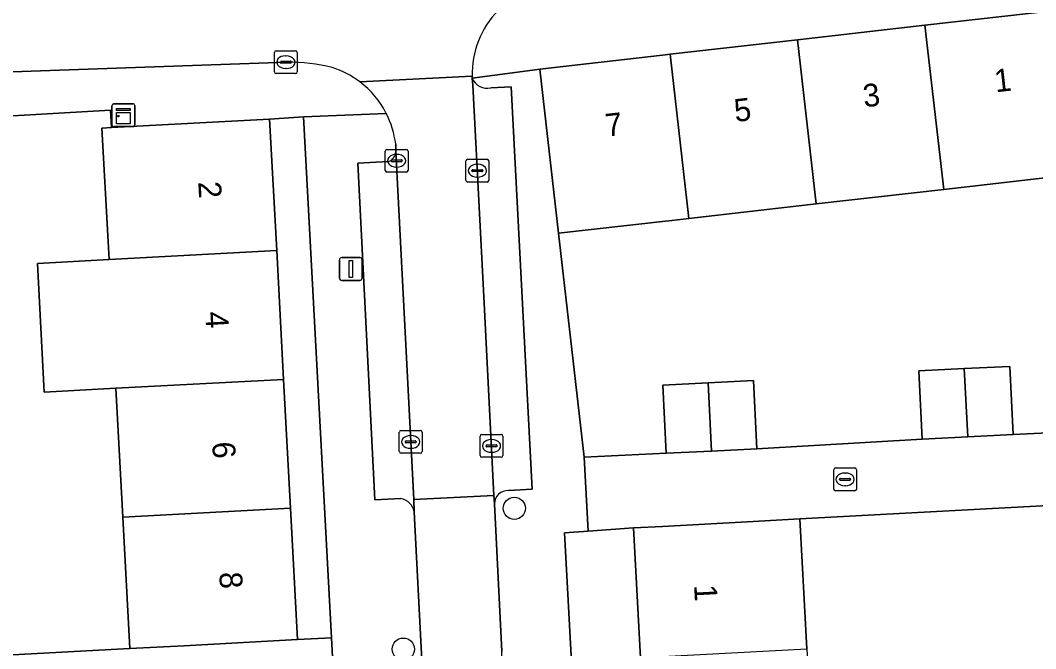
# Model space of a CAD drawing. Extents: x 162250 to 162661, y 380743 to 381606.
# Drawn here: x 162471.8 to 162516.38, y 380866.07 to 380893.67 of the extents above; entities that cross this region are included whole.
import ezdxf

# ---------------------------------------------------------------- set-up
doc = ezdxf.new("R2010")
doc.units = 0
for name, color, linetype in [('IMGEO_Boom', 7, 'Continuous'), ('IMGEO_Erf', 7, 'Continuous'), ('IMGEO_Kast', 7, 'Continuous'), ('IMGEO_Kolk', 7, 'Continuous'), ('IMGEO_Lichtmast', 7, 'Continuous'), ('IMGEO_Muur', 7, 'Continuous'), ('IMGEO_Pand', 7, 'Continuous'), ('IMGEO_Pand_nummerreeks', 7, 'Continuous'), ('IMGEO_Parkeervlak_open', 7, 'Continuous'), ('IMGEO_Rijbaan_lokaal_open', 7, 'Continuous'), ('IMGEO_Voetpad_open', 7, 'Continuous')]:
    doc.layers.add(name, color=color, linetype=linetype)

msp = doc.modelspace()

# ---------------------------------------------------------------- linework, layer by layer
at = {"layer": 'IMGEO_Boom'}
for centre in [(162493.492, 380872.237), (162488.619, 380866.049)]:
    msp.add_circle(centre, 0.489, dxfattribs=at)
at = {"layer": 'IMGEO_Erf'}
for points in [[(162476.003, 380877.506), (162472.856, 380877.338), (162472.553, 380882.993), (162475.699, 380883.161), (162475.657, 380883.948), (162475.388, 380888.933), (162475.802, 380888.955), (162475.764, 380889.728), (162473.498, 380889.596), (162463.611, 380889.016), (162463.383, 380889.008), (162463.524, 380884.867), (162467.402, 380885), (162467.48, 380882.72), (162467.564, 380880.294), (162463.905, 380880.169), (162464.132, 380873.557), (162468.01, 380873.69), (162468.088, 380871.41), (162468.172, 380868.984), (162464.294, 380868.851), (162464.412, 380865.42), (162476.618, 380866.074), (162476.307, 380871.851)], [(162484.236, 380889.431), (162482.75, 380889.328), (162483.06, 380883.556), (162483.364, 380877.9), (162483.668, 380872.246), (162483.979, 380866.47), (162485.462, 380866.549)], [(162518.058, 380886.891), (162512.345, 380886.245), (162506.75, 380885.606), (162501.155, 380884.966), (162500.406, 380884.88), (162500, 380884.834), (162495.438, 380884.313), (162496.559, 380874.478), (162500.151, 380874.654), (162500.005, 380877.65), (162501.998, 380877.747), (162503.992, 380877.845), (162504.138, 380874.849), (162511.4, 380875.277), (162511.253, 380878.273), (162513.247, 380878.371), (162515.24, 380878.468), (162515.387, 380875.472), (162519.087, 380875.653)], [(162500.535, 380837.761), (162500.235, 380843.344), (162500, 380847.679), (162499.934, 380848.927), (162499.634, 380854.509), (162499.333, 380860.091), (162499.032, 380865.673), (162498.723, 380871.373), (162496.735, 380871.229), (162495.691, 380871.164), (162499.625, 380798.455), (162500, 380798.466), (162501.095, 380798.5), (162502.647, 380798.565), (162502.34, 380804.267), (162502.039, 380809.849), (162501.738, 380815.432), (162501.437, 380821.014), (162501.136, 380826.596), (162500.835, 380832.179)]]:
    msp.add_lwpolyline(points, close=True, dxfattribs=at)
msp.add_lwpolyline([(162519.127, 380872.478), (162506.03, 380871.77), (162506.34, 380866.068), (162506.643, 380860.485), (162506.946, 380854.903), (162507.25, 380849.322), (162507.553, 380843.739), (162507.856, 380838.156), (162508.16, 380832.575), (162508.463, 380826.992), (162508.766, 380821.409)], dxfattribs=at)
at = {"layer": 'IMGEO_Kast'}
for p, q in [((162475.827, 380889.074), (162475.827, 380889.915)), ((162475.827, 380889.915), (162475.827, 380889.074)), ((162475.902, 380889.999), (162476.743, 380889.999)), ((162476.743, 380889.999), (162475.902, 380889.999)), ((162476.827, 380889.924), (162476.827, 380889.083)), ((162476.827, 380889.083), (162476.827, 380889.924)), ((162476.752, 380888.999), (162475.911, 380888.999)), ((162475.911, 380888.999), (162476.752, 380888.999))]:
    msp.add_line(p, q, dxfattribs=at)
for points in [[(162476.022, 380889.789), (162476.622, 380889.789), (162476.622, 380889.704), (162476.022, 380889.704), (162476.022, 380889.789)], [(162476.022, 380889.614), (162476.622, 380889.614), (162476.622, 380889.125), (162476.022, 380889.125), (162476.022, 380889.614)]]:
    msp.add_lwpolyline(points, dxfattribs=at)
msp.add_circle((162476.106, 380889.463), 0.0377, dxfattribs=at)
for centre, start, end in [((162475.905, 380889.921), 92.4484, 184.2845), ((162475.905, 380889.921), 92.4484, 184.2845), ((162476.749, 380889.921), 2.4484, 94.2845), ((162476.749, 380889.921), 2.4484, 94.2845), ((162475.905, 380889.077), 182.4484, 274.2845), ((162475.905, 380889.077), 182.4484, 274.2845), ((162476.749, 380889.077), 272.4484, 4.2845), ((162476.749, 380889.077), 272.4484, 4.2845)]:
    msp.add_arc(centre, 0.0779, start, end, dxfattribs=at)
at = {"layer": 'IMGEO_Kolk'}
for p, q in [((162482.962, 380891.404), (162482.962, 380892.256)), ((162483.037, 380892.33), (162483.889, 380892.33)), ((162483.45, 380892.11), (162483.475, 380892.11)), ((162483.963, 380892.256), (162483.963, 380891.404)), ((162483.221, 380891.824), (162483.221, 380891.836)), ((162483.659, 380891.787), (162483.261, 380891.787)), ((162483.264, 380891.873), (162483.662, 380891.873)), ((162483.705, 380891.836), (162483.705, 380891.824)), ((162483.889, 380891.33), (162483.037, 380891.33)), ((162483.473, 380891.55), (162483.448, 380891.55)), ((162487.827, 380887.075), (162487.827, 380887.927)), ((162487.902, 380888.001), (162488.754, 380888.001)), ((162488.315, 380887.781), (162488.34, 380887.781)), ((162488.828, 380887.927), (162488.828, 380887.075)), ((162488.086, 380887.495), (162488.086, 380887.507)), ((162488.524, 380887.458), (162488.126, 380887.458)), ((162488.129, 380887.544), (162488.527, 380887.544)), ((162488.338, 380887.221), (162488.313, 380887.221)), ((162488.57, 380887.507), (162488.57, 380887.495)), ((162491.37, 380886.638), (162491.37, 380887.49)), ((162491.445, 380887.564), (162492.297, 380887.564)), ((162491.858, 380887.344), (162491.883, 380887.344)), ((162492.371, 380887.49), (162492.371, 380886.638)), ((162488.754, 380887.001), (162487.902, 380887.001)), ((162491.629, 380887.058), (162491.629, 380887.07)), ((162492.067, 380887.021), (162491.669, 380887.021)), ((162491.672, 380887.107), (162492.07, 380887.107)), ((162491.881, 380886.784), (162491.856, 380886.784)), ((162492.113, 380887.07), (162492.113, 380887.058)), ((162492.297, 380886.564), (162491.445, 380886.564)), ((162488.443, 380874.728), (162488.443, 380875.58)), ((162488.518, 380875.654), (162489.37, 380875.654)), ((162489.444, 380875.58), (162489.444, 380874.728)), ((162488.702, 380875.148), (162488.702, 380875.16)), ((162489.14, 380875.111), (162488.742, 380875.111)), ((162488.745, 380875.197), (162489.143, 380875.197)), ((162488.931, 380875.434), (162488.956, 380875.434)), ((162489.186, 380875.16), (162489.186, 380875.148)), ((162491.99, 380874.552), (162491.99, 380875.404)), ((162492.065, 380875.478), (162492.917, 380875.478)), ((162492.478, 380875.258), (162492.503, 380875.258)), ((162492.991, 380875.404), (162492.991, 380874.552)), ((162489.37, 380874.654), (162488.518, 380874.654)), ((162488.954, 380874.874), (162488.929, 380874.874)), ((162492.249, 380874.972), (162492.249, 380874.984)), ((162492.687, 380874.935), (162492.289, 380874.935)), ((162492.292, 380875.021), (162492.69, 380875.021)), ((162492.501, 380874.698), (162492.476, 380874.698)), ((162492.733, 380874.984), (162492.733, 380874.972)), ((162492.917, 380874.478), (162492.065, 380874.478)), ((162507.513, 380873.081), (162507.513, 380873.933)), ((162507.588, 380874.007), (162508.44, 380874.007)), ((162508.001, 380873.787), (162508.026, 380873.787)), ((162508.514, 380873.933), (162508.514, 380873.081)), ((162507.772, 380873.501), (162507.772, 380873.513)), ((162508.21, 380873.464), (162507.812, 380873.464)), ((162507.815, 380873.55), (162508.213, 380873.55)), ((162508.256, 380873.513), (162508.256, 380873.501)), ((162508.44, 380873.007), (162507.588, 380873.007)), ((162508.024, 380873.227), (162507.999, 380873.227))]:
    msp.add_line(p, q, dxfattribs=at)
for points in [[(162482.962, 380891.404), (162482.962, 380892.256)], [(162483.037, 380892.33), (162483.889, 380892.33)], [(162483.963, 380892.256), (162483.963, 380891.404)], [(162483.889, 380891.33), (162483.037, 380891.33)], [(162487.827, 380887.075), (162487.827, 380887.927)], [(162487.902, 380888.001), (162488.754, 380888.001)], [(162488.828, 380887.927), (162488.828, 380887.075)], [(162491.37, 380886.638), (162491.37, 380887.49)], [(162491.445, 380887.564), (162492.297, 380887.564)], [(162492.371, 380887.49), (162492.371, 380886.638)], [(162488.754, 380887.001), (162487.902, 380887.001)], [(162492.297, 380886.564), (162491.445, 380886.564)], [(162488.443, 380874.728), (162488.443, 380875.58)], [(162488.518, 380875.654), (162489.37, 380875.654)], [(162489.444, 380875.58), (162489.444, 380874.728)], [(162491.99, 380874.552), (162491.99, 380875.404)], [(162492.065, 380875.478), (162492.917, 380875.478)], [(162492.991, 380875.404), (162492.991, 380874.552)], [(162489.37, 380874.654), (162488.518, 380874.654)], [(162492.917, 380874.478), (162492.065, 380874.478)], [(162507.513, 380873.081), (162507.513, 380873.933)], [(162507.588, 380874.007), (162508.44, 380874.007)], [(162508.514, 380873.933), (162508.514, 380873.081)], [(162508.44, 380873.007), (162507.588, 380873.007)]]:
    msp.add_lwpolyline(points, dxfattribs=at)
for centre, radius, start, end in [((162483.039, 380892.254), 0.0765, 91.552, 178.448), ((162483.039, 380892.254), 0.0765, 91.552, 178.448), ((162483.887, 380892.254), 0.0765, 1.552, 88.448), ((162483.887, 380892.254), 0.0765, 1.552, 88.448), ((162483.261, 380891.833), 0.0403, 85.8775, 175.7526), ((162483.258, 380891.823), 0.0366, 178.938, 274.7102), ((162483.662, 380891.83), 0.043, 264.8664, 352.4533), ((162483.666, 380891.835), 0.0386, 1.7309, 96.639), ((162483.039, 380891.406), 0.0765, 181.552, 268.448), ((162483.039, 380891.406), 0.0765, 181.552, 268.448), ((162483.887, 380891.406), 0.0765, 271.552, 358.448), ((162483.887, 380891.406), 0.0765, 271.552, 358.448), ((162487.904, 380887.925), 0.0765, 91.552, 178.448), ((162487.904, 380887.925), 0.0765, 91.552, 178.448), ((162488.752, 380887.925), 0.0765, 1.552, 88.448), ((162488.752, 380887.925), 0.0765, 1.552, 88.448), ((162488.126, 380887.504), 0.0403, 85.8775, 175.7526), ((162488.123, 380887.494), 0.0366, 178.938, 274.7102), ((162488.527, 380887.501), 0.043, 264.8664, 352.4533), ((162488.531, 380887.506), 0.0386, 1.7309, 96.639), ((162491.447, 380887.488), 0.0765, 91.552, 178.448), ((162491.447, 380887.488), 0.0765, 91.552, 178.448), ((162492.295, 380887.488), 0.0765, 1.552, 88.448), ((162492.295, 380887.488), 0.0765, 1.552, 88.448), ((162487.904, 380887.077), 0.0765, 181.552, 268.448), ((162487.904, 380887.077), 0.0765, 181.552, 268.448), ((162488.752, 380887.077), 0.0765, 271.552, 358.448), ((162488.752, 380887.077), 0.0765, 271.552, 358.448), ((162491.669, 380887.067), 0.0403, 85.8775, 175.7526), ((162491.666, 380887.057), 0.0366, 178.938, 274.7102), ((162492.07, 380887.064), 0.043, 264.8664, 352.4533), ((162492.074, 380887.069), 0.0386, 1.7309, 96.639), ((162491.447, 380886.64), 0.0765, 181.552, 268.448), ((162491.447, 380886.64), 0.0765, 181.552, 268.448), ((162492.295, 380886.64), 0.0765, 271.552, 358.448), ((162492.295, 380886.64), 0.0765, 271.552, 358.448), ((162488.52, 380875.578), 0.0765, 91.552, 178.448), ((162488.52, 380875.578), 0.0765, 91.552, 178.448), ((162489.368, 380875.578), 0.0765, 1.552, 88.448), ((162489.368, 380875.578), 0.0765, 1.552, 88.448), ((162488.742, 380875.157), 0.0403, 85.8775, 175.7526), ((162488.739, 380875.147), 0.0366, 178.938, 274.7102), ((162489.143, 380875.154), 0.043, 264.8664, 352.4533), ((162489.147, 380875.159), 0.0386, 1.7309, 96.639), ((162492.067, 380875.402), 0.0765, 91.552, 178.448), ((162492.067, 380875.402), 0.0765, 91.552, 178.448), ((162492.915, 380875.402), 0.0765, 1.552, 88.448), ((162492.915, 380875.402), 0.0765, 1.552, 88.448), ((162488.52, 380874.73), 0.0765, 181.552, 268.448), ((162488.52, 380874.73), 0.0765, 181.552, 268.448), ((162489.368, 380874.73), 0.0765, 271.552, 358.448), ((162489.368, 380874.73), 0.0765, 271.552, 358.448), ((162492.289, 380874.981), 0.0403, 85.8775, 175.7526), ((162492.286, 380874.971), 0.0366, 178.938, 274.7102), ((162492.69, 380874.978), 0.043, 264.8664, 352.4533), ((162492.694, 380874.983), 0.0386, 1.7309, 96.639), ((162492.067, 380874.554), 0.0765, 181.552, 268.448), ((162492.067, 380874.554), 0.0765, 181.552, 268.448), ((162492.915, 380874.554), 0.0765, 271.552, 358.448), ((162492.915, 380874.554), 0.0765, 271.552, 358.448), ((162507.59, 380873.931), 0.0765, 91.552, 178.448), ((162507.59, 380873.931), 0.0765, 91.552, 178.448), ((162508.438, 380873.931), 0.0765, 1.552, 88.448), ((162508.438, 380873.931), 0.0765, 1.552, 88.448), ((162507.812, 380873.51), 0.0403, 85.8775, 175.7526), ((162507.809, 380873.5), 0.0366, 178.938, 274.7102), ((162508.213, 380873.507), 0.043, 264.8664, 352.4533), ((162508.217, 380873.512), 0.0386, 1.7309, 96.639), ((162507.59, 380873.083), 0.0765, 181.552, 268.448), ((162507.59, 380873.083), 0.0765, 181.552, 268.448), ((162508.438, 380873.083), 0.0765, 271.552, 358.448), ((162508.438, 380873.083), 0.0765, 271.552, 358.448)]:
    msp.add_arc(centre, radius, start, end, dxfattribs=at)
for centre, major_axis, ratio, start_param, end_param in [((162483.449, 380891.83), (-0.387, 0.002), 0.722429, 4.712389, 7.853982), ((162483.474, 380891.83), (-0.39, 0.002), 0.717154, 1.570796, 4.712389), ((162488.314, 380887.501), (-0.387, 0.002), 0.722429, 4.712389, 7.853982), ((162488.339, 380887.501), (-0.39, 0.002), 0.717154, 1.570796, 4.712389), ((162491.857, 380887.064), (-0.387, 0.002), 0.722429, 4.712389, 7.853982), ((162491.882, 380887.064), (-0.39, 0.002), 0.717154, 1.570796, 4.712389), ((162488.93, 380875.154), (-0.387, 0.002), 0.722429, 4.712389, 7.853982), ((162488.955, 380875.154), (-0.39, 0.002), 0.717154, 1.570796, 4.712389), ((162492.477, 380874.978), (-0.387, 0.002), 0.722429, 4.712389, 7.853982), ((162492.502, 380874.978), (-0.39, 0.002), 0.717154, 1.570796, 4.712389), ((162508, 380873.507), (-0.387, 0.002), 0.722429, 4.712389, 7.853982), ((162508.025, 380873.507), (-0.39, 0.002), 0.717154, 1.570796, 4.712389)]:
    msp.add_ellipse(centre, major_axis=major_axis, ratio=ratio, start_param=start_param, end_param=end_param, dxfattribs=at)
at = {"layer": 'IMGEO_Lichtmast'}
for p, q in [((162485.815, 380882.348), (162485.815, 380883.148)), ((162485.815, 380883.148), (162485.815, 380882.348)), ((162485.915, 380883.248), (162486.705, 380883.248)), ((162486.705, 380883.248), (162485.915, 380883.248)), ((162486.805, 380883.148), (162486.805, 380882.348)), ((162486.805, 380882.348), (162486.805, 380883.148)), ((162486.705, 380882.248), (162485.915, 380882.248)), ((162485.915, 380882.248), (162486.705, 380882.248))]:
    msp.add_line(p, q, dxfattribs=at)
msp.add_lwpolyline([(162486.235, 380883.123), (162486.385, 380883.123), (162486.385, 380882.373), (162486.235, 380882.373), (162486.235, 380883.123)], dxfattribs=at)
for centre, start, end in [((162485.915, 380883.148), 90, 180), ((162485.915, 380883.148), 90, 180), ((162486.705, 380883.148), 0, 90), ((162486.705, 380883.148), 360, 90), ((162485.915, 380882.348), 180, 270), ((162485.915, 380882.348), 180, 270), ((162486.705, 380882.348), 270, 0), ((162486.705, 380882.348), 270, 0)]:
    msp.add_arc(centre, 0.1, start, end, dxfattribs=at)
at = {"layer": 'IMGEO_Muur'}
msp.add_lwpolyline([(162475.802, 380888.955), (162475.764, 380889.728), (162473.498, 380889.596)], dxfattribs=at)
at = {"layer": 'IMGEO_Pand'}
for points in [[(162511.52, 380893.448), (162512.345, 380886.245), (162518.058, 380886.891), (162517.802, 380889.133), (162517.236, 380894.1)], [(162511.52, 380893.448), (162505.925, 380892.811), (162506.75, 380885.606), (162512.345, 380886.245)], [(162506.75, 380885.606), (162505.925, 380892.811), (162500.33, 380892.174), (162501.155, 380884.966)], [(162501.155, 380884.966), (162500.33, 380892.174), (162500, 380892.136), (162494.616, 380891.523), (162495.438, 380884.313), (162500, 380884.834), (162500.406, 380884.88)], [(162475.699, 380883.161), (162483.06, 380883.556), (162482.75, 380889.328), (162475.802, 380888.955), (162475.388, 380888.933), (162475.657, 380883.948)], [(162476.003, 380877.506), (162483.364, 380877.9), (162483.06, 380883.556), (162475.699, 380883.161), (162472.553, 380882.993), (162472.856, 380877.338)], [(162513.247, 380878.371), (162511.253, 380878.273), (162511.4, 380875.277), (162513.394, 380875.375)], [(162513.247, 380878.371), (162513.394, 380875.375), (162515.387, 380875.472), (162515.24, 380878.468)], [(162476.003, 380877.506), (162476.307, 380871.851), (162483.668, 380872.246), (162483.364, 380877.9)], [(162501.998, 380877.747), (162502.145, 380874.751), (162504.138, 380874.849), (162503.992, 380877.845)], [(162501.998, 380877.747), (162500.005, 380877.65), (162500.151, 380874.654), (162502.145, 380874.751)], [(162483.668, 380872.246), (162476.307, 380871.851), (162476.618, 380866.074), (162478.987, 380866.201), (162483.979, 380866.47)], [(162499.032, 380865.673), (162500, 380865.725), (162506.34, 380866.068), (162506.03, 380871.77), (162503.716, 380871.645), (162500, 380871.443), (162498.723, 380871.373)]]:
    msp.add_lwpolyline(points, close=True, dxfattribs=at)
at = {"layer": 'IMGEO_Parkeervlak_open'}
for points in [[(162491.648, 380891.122), (162491.675, 380890.818), (162492.17, 380881.246), (162492.599, 380872.801), (162492.618, 380872.433)], [(162493.232, 380873.016), (162494.273, 380873.081), (162493.349, 380890.743), (162492.46, 380890.703)], [(162489.101, 380872.087), (162489.073, 380872.622), (162488.283, 380887.891)], [(162487.972, 380887.465), (162486.624, 380887.395), (162487.368, 380872.602), (162488.51, 380872.667)]]:
    msp.add_lwpolyline(points, dxfattribs=at)
for centre, radius, start, end in [((162492.293, 380891.376), 0.694, 201.5008, 283.9109), ((162487.812, 380887.908), 0.471, 289.8092, 357.9284), ((162493.212, 380872.422), 0.594, 88.0933, 178.9397), ((162488.368, 380871.931), 0.749, 11.9874, 79.089)]:
    msp.add_arc(centre, radius, start, end, dxfattribs=at)
at = {"layer": 'IMGEO_Rijbaan_lokaal_open'}
for points in [[(162439.842, 380890.44), (162444.978, 380890.665), (162455.661, 380890.851), (162457.816, 380890.926), (162463.857, 380891.137), (162468.515, 380891.299), (162483.523, 380891.833)], [(162491.675, 380890.818), (162491.648, 380891.122), (162491.645, 380891.208), (162486.708, 380890.966)], [(162486.708, 380890.966), (162491.645, 380891.208)], [(162488.283, 380888.236), (162488.283, 380887.891), (162489.073, 380872.622), (162492.599, 380872.801), (162492.17, 380881.246), (162491.675, 380890.818)]]:
    msp.add_lwpolyline(points, dxfattribs=at)
msp.add_lwpolyline([(162492.944, 380865.944), (162492.618, 380872.433), (162492.599, 380872.801), (162489.073, 380872.622), (162489.101, 380872.087), (162489.436, 380865.547), (162489.379, 380865.385), (162492.965, 380865.526)], close=True, dxfattribs=at)
for centre, radius, start, end in [((162495.589, 380891.321), 3.946, 135.5373, 181.6448), ((162483.57, 380883.869), 7.964, 76.0425, 90.3385), ((162484.271, 380887.762), 4.026, 52.75, 72.3634), ((162484.252, 380887.728), 4.064, 27.0939, 52.8172), ((162484.261, 380887.734), 4.053, 7.1116, 27.0759)]:
    msp.add_arc(centre, radius, start, end, dxfattribs=at)
at = {"layer": 'IMGEO_Voetpad_open'}
for points in [[(162491.645, 380891.208), (162491.648, 380891.122), (162493.634, 380891.39), (162494.616, 380891.523), (162500, 380892.136), (162500.33, 380892.174), (162505.925, 380892.811), (162511.52, 380893.448), (162517.236, 380894.1), (162520.08, 380894.444), (162532.211, 380895.911), (162532.466, 380894.986), (162539.411, 380896.403)], [(162483.523, 380891.833), (162468.515, 380891.299), (162463.857, 380891.137), (162463.872, 380890.638), (162457.831, 380890.427), (162457.816, 380890.926), (162455.661, 380890.851), (162444.978, 380890.665), (162439.842, 380890.44)], [(162495.691, 380871.164), (162496.735, 380871.229), (162496.559, 380874.478), (162495.438, 380884.313), (162494.616, 380891.523), (162493.634, 380891.39), (162491.648, 380891.122)], [(162492.46, 380890.703), (162493.349, 380890.743), (162494.273, 380873.081), (162493.232, 380873.016)], [(162436.137, 380887.782), (162436.094, 380887.375), (162438.964, 380887.383), (162442.046, 380887.428), (162449.389, 380887.538), (162449.36, 380888.532), (162461.426, 380888.942), (162463.383, 380889.008), (162463.611, 380889.016), (162473.498, 380889.596), (162475.764, 380889.728), (162475.802, 380888.955), (162482.75, 380889.328), (162484.236, 380889.431), (162487.87, 380889.579)], [(162487.87, 380889.579), (162484.236, 380889.431), (162485.462, 380866.549), (162485.538, 380865.136), (162488.037, 380818.506), (162489.147, 380797.656), (162487.656, 380797.55), (162486.74, 380797.501), (162486.836, 380795.589), (162487.044, 380791.747), (162487.308, 380785.923), (162487.775, 380777.333), (162492.299, 380777.594), (162491.633, 380791.217), (162492.725, 380791.274)], [(162488.283, 380887.891), (162488.283, 380888.236)], [(162488.51, 380872.667), (162487.368, 380872.602), (162486.624, 380887.395), (162487.972, 380887.465)], [(162519.087, 380875.653), (162515.387, 380875.472), (162513.394, 380875.375), (162511.4, 380875.277), (162504.138, 380874.849), (162502.145, 380874.751), (162500.151, 380874.654), (162496.559, 380874.478), (162496.735, 380871.229), (162498.723, 380871.373), (162500, 380871.443), (162503.716, 380871.645), (162506.03, 380871.77), (162519.127, 380872.478)], [(162492.618, 380872.433), (162492.944, 380865.944)], [(162489.379, 380865.385), (162489.436, 380865.547), (162489.101, 380872.087)], [(162496.225, 380798.581), (162496.36, 380795.645), (162496.445, 380793.785), (162496.544, 380791.858), (162499.481, 380792.01), (162499.931, 380782.983), (162500.205, 380778.05), (162502.201, 380778.165), (162501.726, 380786.77), (162501.383, 380792.633), (162501.171, 380796.468), (162501.095, 380798.5), (162500, 380798.466), (162499.625, 380798.455), (162495.691, 380871.164)], [(162464.301, 380863.978), (162472.756, 380864.438), (162476.692, 380864.644), (162479.036, 380864.786), (162484.028, 380865.055), (162485.538, 380865.136), (162485.462, 380866.549), (162483.979, 380866.47), (162478.987, 380866.201), (162476.618, 380866.074), (162464.412, 380865.42)]]:
    msp.add_lwpolyline(points, dxfattribs=at)
for centre, radius, start, end in [((162495.589, 380891.321), 3.946, 135.5373, 181.6448), ((162483.57, 380883.869), 7.964, 76.0425, 90.3385), ((162484.271, 380887.762), 4.026, 52.75, 72.3634), ((162484.252, 380887.728), 4.064, 27.0939, 52.8172), ((162492.293, 380891.376), 0.694, 201.5008, 283.9109), ((162484.261, 380887.734), 4.053, 7.1116, 27.0759), ((162487.812, 380887.908), 0.471, 289.8092, 357.9284), ((162493.212, 380872.422), 0.594, 88.0933, 178.9397), ((162488.368, 380871.931), 0.749, 11.9874, 79.089)]:
    msp.add_arc(centre, radius, start, end, dxfattribs=at)

# ---------------------------------------------------------------- texts
at = {"layer": 'IMGEO_Pand_nummerreeks'}
for s, rotation, p in [('1', 6.4994, (162514.62, 380890.502)), ('3', 6.4994, (162508.852, 380889.844)), ('5', 6.4994, (162503.197, 380889.2)), ('7', 6.4994, (162497.542, 380888.556)), ('2', 273.0776, (162479.614, 380886.571)), ('4', 273.0776, (162479.921, 380880.855)), ('6', 273.0776, (162480.228, 380875.14)), ('8', 273.0776, (162480.536, 380869.422)), ('1', 273.085, (162501.382, 380868.869))]:
    msp.add_text(s, height=1, rotation=rotation, dxfattribs=at).set_placement(p)

doc.saveas('drawing.dxf')
